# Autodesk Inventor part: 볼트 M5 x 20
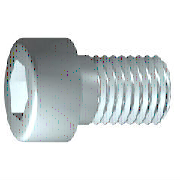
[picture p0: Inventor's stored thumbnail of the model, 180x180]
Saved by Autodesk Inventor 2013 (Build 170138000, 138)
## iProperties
Created: 2012-02
Part Number: 볼트 M5 x 20
Material: 스테인리스강
Description: 6각 소켓 머리 캡 나사
Document SubType Name: Modeling
Standard: ISO 4762
Designer: mduedu
Standard Revision: Fourth edition 2004-03-01
Standards Organization: ISO
Language: ko-KR
Size Designation: M5 x 20
Categories: <MemberInstance><Categories><Category DisplayName="조임쇠" InternalName="e4da775c-781d-43d5-af7c-5136215cf5a6" Mnemonic="FSTN"><Category DisplayName="볼트" InternalN
Density: 7.75 g/cm^3
Mass: 4.89344 g
Surface Area: 5.88237 cm^2
Volume: 0.631412 cm^3
IsCustomPart: 0
Author: mduedu
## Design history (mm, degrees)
sketch "스케치1"
  geometry: L1 (-1.167, 0)-(20, 0); L2 (20, 0)-(20, 2.5); L3 (20, 2.5)-(2, 2.5); L4 (2, 2.5)-(1.509, 2.5); L5 (1.509, 2.5)-(0, 2.5); L6 (0, 2.5)-(0, 4.25); L7 (0, 4.25)-(-5, 4.25); L8 (-5, 4.25)-(-5, 2.309); L9 (-5, 2.309)-(-2.5, 2.309); L10 (-2.5, 2.309)-(-1.167, 0); L11 (-10, 0)-(25, 0) reference; L12 (0, -0.85)-(0, 5.1) reference; L13 (2, 2.5)-(0, 2.5)
  constraints: 22 end point, 6 parallel, 2 collinear, 2 perpendicular, 1 horizontal, 1 point on line
  dimensions: "d1" = 18 distance from line of L3.end L2 (= GEL); "d2" = 0.49086 distance of L4.end L3.end (computed from GAL); "d3" = 5 distance between parallel lines of L8 L6 (= KOH); "d4" = 2.5 distance of L8.end L9.end (= INTI); "d5" = 60 deg angle of L10 L1; "d6" = 5 diameter of L3 L1 (= GD); "d7" = 5 diameter of L5 L1 (= BDM); "d8" = 4.6188 diameter of L9 L1 (= 1.1547 x SW); "d9" = 8.5 diameter of L7 L1 (= KOD); "d26" = 20 distance between parallel lines of L12 L2 (= NLG)
revolve "본체" sketch "스케치1" stored, may be unused: angle "d10" = 90 deg
sketch "스케치2"
  geometry: L1 (0, -5.95)-(0, 5.95) reference; L2 (-5.95, 0)-(5.95, 0) reference; L3 (2.309, 0)-(1.155, -2); L4 (1.155, -2)-(-1.155, -2); L5 (-1.155, -2)-(-2.309, 0); L6 (-2.309, 0)-(-1.155, 2); L7 (-1.155, 2)-(1.155, 2); L8 (1.155, 2)-(2.309, 0); 2 further points
  constraints: 12 end point, 1 coincident, 1 horizontal alignment, 1 point on line, 12 other
extrude "슬롯" join sketch "스케치2" stored distance "d11" = 10; taper "d12" = 0 deg
workplane "Work Plane1"
fillet "Fillet2" dims "d30" = 0.1 (= R)
body "Solid1"
fillet "모깎기1" dims "d17" = 0.5 (= RR)
feature "스레드" dims "d13" = 18 (= GEL), "d14" = 0
chamfer "모따기1" distance "d15" = 0.49076 (= -0.5 x SPD + 0.5 x GD); stored, may be unused: second distance "d16" = 0.49076 (= GUL), angle "d27" = 45 deg
other parameters: "GD" = 5 [user parameter; used in 2 equation terms], "NLG" = 20 [user parameter; used in 1 equation term], "GEL" = 18 [user parameter; used in 2 equation terms], "KOD" = 8.5 [user parameter; used in 1 equation term], "KOH" = 5 [user parameter; used in 1 equation term], "INTI" = 2.5 [user parameter; used in 1 equation term], "GAL" = 0.49076 (= 0.61345 x PTC) [user parameter; used in 1 equation term], "GUL" = 0.49076 (= 0.61345 x PTC) [user parameter; used in 1 equation term], "BDM" = 5 (= NND) [user parameter; used in 1 equation term], "SW" = 4 [user parameter; used in 2 equation terms], "RR" = 0.5 [user parameter; used in 1 equation term], "SPD" = 4.01848 (= NND - 1.2269 x PTC) [user parameter; used in 1 equation term], "d19" = 0, "d28" = 0, "d29" = 0, "R" = 0.1 [user parameter; used in 1 equation term], "TOA" = 30 deg [user parameter], "GD1" = 4.01848 (= THREADDIA - 1.2269 x PTC) [user parameter], "THREADDIA" = 5 [user parameter; used in 1 equation term], "FAWI" = 45 deg [user parameter], "TPU" = 12.5 (computed from PTC) [user parameter], "PTC" = 0.8 [user parameter; used in 5 equation terms], "NND" = 5 [user parameter; used in 2 equation terms], "E0" = 4.62 (= 1.155 x SW) [user parameter]
